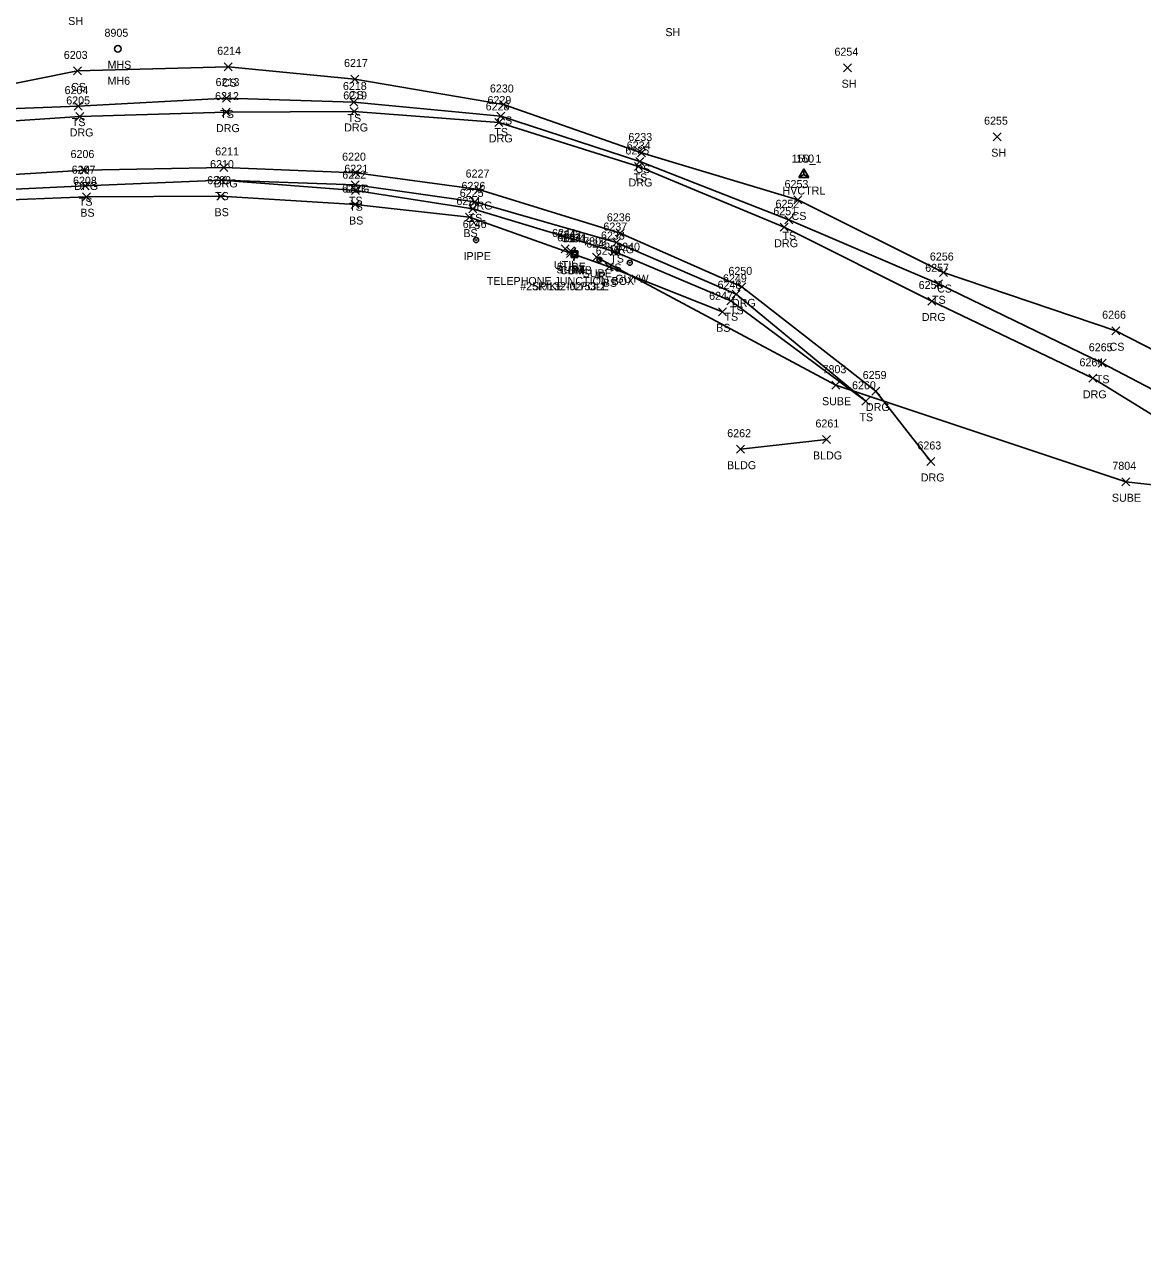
# Model space of a CAD drawing. Extents: x 1678863 to 1683592, y 407783 to 418211.
# Drawn here: x 1679504.2 to 1679783.6, y 409222.9 to 409532.2 of the extents above; entities that cross this region are included whole.
import ezdxf

# ---------------------------------------------------------------- set-up
doc = ezdxf.new("R2010")
doc.units = 0
for name, color, linetype in [('C_A', 7, 'Continuous'), ('C_C', 7, 'Continuous'), ('C_I', 7, 'Continuous'), ('CPBM', 7, 'Continuous'), ('CPSM', 7, 'Continuous'), ('L_A', 7, 'Continuous'), ('L_I', 7, 'Continuous'), ('L_TIC', 7, 'Continuous'), ('LBC', 7, 'Continuous'), ('LELB', 7, 'Continuous'), ('M_A', 7, 'Continuous'), ('M_I', 7, 'Continuous'), ('MPIP', 7, 'Continuous'), ('MPIR', 7, 'Continuous'), ('R_A', 7, 'Continuous'), ('R_I', 7, 'Continuous'), ('R_TIC', 7, 'Continuous'), ('RDG', 7, 'Continuous'), ('U_A', 7, 'Continuous'), ('U_C', 7, 'Continuous'), ('U_I', 7, 'Continuous'), ('U_TIC', 7, 'Continuous'), ('UDEFAULT', 7, 'Continuous'), ('UE', 7, 'Continuous'), ('UP', 7, 'Continuous'), ('UPGW', 7, 'Continuous'), ('USMH', 7, 'Continuous')]:
    doc.layers.add(name, color=color, linetype=linetype)

msp = doc.modelspace()

# ---------------------------------------------------------------- linework, layer by layer
at = {"layer": 'CPBM'}
for p, q in [((1679641.12, 409474.36), (1679641.12, 409475.36)), ((1679641.12, 409475.36), (1679642.12, 409475.36)), ((1679642.12, 409474.36), (1679641.12, 409474.36)), ((1679641.62, 409474.86), (1679641.62, 409474.86)), ((1679641.62, 409474.86), (1679641.62, 409474.86)), ((1679642.12, 409475.36), (1679642.12, 409474.36))]:
    msp.add_line(p, q, dxfattribs=at)
at = {"layer": 'CPSM'}
for p, q in [((1679697.69, 409494.05), (1679698.94, 409496.21)), ((1679697.69, 409494.05), (1679698.94, 409496.21)), ((1679697.69, 409494.05), (1679698.94, 409496.21)), ((1679697.69, 409494.05), (1679698.94, 409496.21)), ((1679697.69, 409494.05), (1679698.94, 409496.21)), ((1679697.69, 409494.05), (1679698.94, 409496.21)), ((1679697.69, 409494.05), (1679698.94, 409496.21)), ((1679697.69, 409494.05), (1679698.94, 409496.21)), ((1679697.69, 409494.05), (1679698.94, 409496.21)), ((1679697.69, 409494.05), (1679698.94, 409494.77)), ((1679697.69, 409494.05), (1679698.94, 409494.77)), ((1679697.69, 409494.05), (1679698.94, 409494.77)), ((1679697.69, 409494.05), (1679698.94, 409494.77)), ((1679697.69, 409494.05), (1679698.94, 409494.77)), ((1679697.69, 409494.05), (1679698.94, 409494.77)), ((1679697.69, 409494.05), (1679698.94, 409494.77)), ((1679697.69, 409494.05), (1679698.94, 409494.77)), ((1679697.69, 409494.05), (1679698.94, 409494.77)), ((1679700.19, 409494.05), (1679698.94, 409496.21)), ((1679698.94, 409494.77), (1679698.94, 409496.21)), ((1679700.19, 409494.05), (1679698.94, 409496.21)), ((1679698.94, 409494.77), (1679698.94, 409496.21)), ((1679700.19, 409494.05), (1679698.94, 409496.21)), ((1679698.94, 409494.77), (1679698.94, 409496.21)), ((1679700.19, 409494.05), (1679698.94, 409496.21)), ((1679698.94, 409494.77), (1679698.94, 409496.21)), ((1679700.19, 409494.05), (1679698.94, 409496.21)), ((1679698.94, 409494.77), (1679698.94, 409496.21)), ((1679700.19, 409494.05), (1679698.94, 409496.21)), ((1679698.94, 409494.77), (1679698.94, 409496.21)), ((1679700.19, 409494.05), (1679698.94, 409496.21)), ((1679698.94, 409494.77), (1679698.94, 409496.21)), ((1679700.19, 409494.05), (1679698.94, 409496.21)), ((1679698.94, 409494.77), (1679698.94, 409496.21)), ((1679700.19, 409494.05), (1679698.94, 409496.21)), ((1679698.94, 409494.77), (1679698.94, 409496.21)), ((1679698.94, 409494.77), (1679698.94, 409494.77)), ((1679698.94, 409494.77), (1679700.19, 409494.05)), ((1679698.94, 409494.77), (1679698.94, 409494.77)), ((1679698.94, 409494.77), (1679700.19, 409494.05)), ((1679698.94, 409494.77), (1679698.94, 409494.77)), ((1679698.94, 409494.77), (1679700.19, 409494.05)), ((1679698.94, 409494.77), (1679698.94, 409494.77)), ((1679698.94, 409494.77), (1679700.19, 409494.05)), ((1679698.94, 409494.77), (1679698.94, 409494.77)), ((1679698.94, 409494.77), (1679700.19, 409494.05)), ((1679698.94, 409494.77), (1679698.94, 409494.77)), ((1679698.94, 409494.77), (1679700.19, 409494.05)), ((1679698.94, 409494.77), (1679698.94, 409494.77)), ((1679698.94, 409494.77), (1679700.19, 409494.05)), ((1679698.94, 409494.77), (1679698.94, 409494.77)), ((1679698.94, 409494.77), (1679700.19, 409494.05)), ((1679698.94, 409494.77), (1679698.94, 409494.77)), ((1679698.94, 409494.77), (1679700.19, 409494.05)), ((1679697.69, 409494.05), (1679700.19, 409494.05)), ((1679697.69, 409494.05), (1679700.19, 409494.05)), ((1679697.69, 409494.05), (1679700.19, 409494.05)), ((1679697.69, 409494.05), (1679700.19, 409494.05)), ((1679697.69, 409494.05), (1679700.19, 409494.05)), ((1679697.69, 409494.05), (1679700.19, 409494.05)), ((1679697.69, 409494.05), (1679700.19, 409494.05)), ((1679697.69, 409494.05), (1679700.19, 409494.05)), ((1679697.69, 409494.05), (1679700.19, 409494.05))]:
    msp.add_line(p, q, dxfattribs=at)
at = {"layer": 'L_TIC'}
for points in [[(1679554.06, 409520.72), (1679556.06, 409522.72)], [(1679556.06, 409520.72), (1679554.06, 409522.72)], [(1679708.92, 409520.48), (1679710.92, 409522.48)], [(1679710.92, 409520.48), (1679708.92, 409522.48)], [(1679516.35, 409519.68), (1679518.35, 409521.68)], [(1679518.35, 409519.68), (1679516.35, 409521.68)], [(1679585.76, 409517.66), (1679587.76, 409519.66)], [(1679587.76, 409517.66), (1679585.76, 409519.66)], [(1679553.65, 409512.89), (1679555.65, 409514.89)], [(1679555.65, 409512.89), (1679553.65, 409514.89)], [(1679585.48, 409511.91), (1679587.48, 409513.91)], [(1679587.48, 409511.91), (1679585.48, 409513.91)], [(1679622.89, 409511.29), (1679624.89, 409513.29)], [(1679624.89, 409511.29), (1679622.89, 409513.29)], [(1679516.55, 409510.88), (1679518.55, 409512.88)], [(1679518.55, 409510.88), (1679516.55, 409512.88)], [(1679622.19, 409508.4), (1679624.19, 409510.4)], [(1679624.19, 409508.4), (1679622.19, 409510.4)], [(1679746.33, 409503.24), (1679748.33, 409505.24)], [(1679748.33, 409503.24), (1679746.33, 409505.24)], [(1679657.4, 409499.17), (1679659.4, 409501.17)], [(1679659.4, 409499.17), (1679657.4, 409501.17)], [(1679657, 409497.05), (1679659, 409499.05)], [(1679659, 409497.05), (1679657, 409499.05)], [(1679518.31, 409490.99), (1679520.31, 409492.99)], [(1679520.31, 409490.99), (1679518.31, 409492.99)], [(1679552.37, 409492.38), (1679554.37, 409494.38)], [(1679554.37, 409492.38), (1679552.37, 409494.38)], [(1679552.37, 409492.38), (1679554.37, 409494.38)], [(1679554.37, 409492.38), (1679552.37, 409494.38)], [(1679585.84, 409491.23), (1679587.84, 409493.23)], [(1679587.84, 409491.23), (1679585.84, 409493.23)], [(1679585.89, 409489.75), (1679587.89, 409491.75)], [(1679587.89, 409489.75), (1679585.89, 409491.75)], [(1679518.65, 409488.23), (1679520.65, 409490.23)], [(1679520.65, 409488.23), (1679518.65, 409490.23)], [(1679552.2, 409488.37), (1679554.2, 409490.37)], [(1679554.2, 409488.37), (1679552.2, 409490.37)], [(1679585.83, 409486.28), (1679587.83, 409488.28)], [(1679587.83, 409486.28), (1679585.83, 409488.28)], [(1679615.75, 409486.94), (1679617.75, 409488.94)], [(1679617.75, 409486.94), (1679615.75, 409488.94)], [(1679696.46, 409487.42), (1679698.46, 409489.42)], [(1679698.46, 409487.42), (1679696.46, 409489.42)], [(1679615.25, 409485.17), (1679617.25, 409487.17)], [(1679617.25, 409485.17), (1679615.25, 409487.17)], [(1679614.42, 409483.14), (1679616.42, 409485.14)], [(1679616.42, 409483.14), (1679614.42, 409485.14)], [(1679694.2, 409482.47), (1679696.2, 409484.47)], [(1679696.2, 409482.47), (1679694.2, 409484.47)], [(1679650.56, 409474.53), (1679652.56, 409476.53)], [(1679652.56, 409474.53), (1679650.56, 409476.53)], [(1679651.16, 409476.77), (1679653.16, 409478.77)], [(1679653.16, 409476.77), (1679651.16, 409478.77)], [(1679649.26, 409470.71), (1679651.26, 409472.71)], [(1679651.26, 409470.71), (1679649.26, 409472.71)], [(1679732.85, 409469.28), (1679734.85, 409471.28)], [(1679734.85, 409469.28), (1679732.85, 409471.28)], [(1679731.61, 409466.46), (1679733.61, 409468.46)], [(1679733.61, 409466.46), (1679731.61, 409468.46)], [(1679679.71, 409462.23), (1679681.71, 409464.23)], [(1679681.71, 409462.23), (1679679.71, 409464.23)], [(1679681.07, 409463.84), (1679683.07, 409465.84)], [(1679683.07, 409463.84), (1679681.07, 409465.84)], [(1679677.6, 409459.46), (1679679.6, 409461.46)], [(1679679.6, 409459.46), (1679677.6, 409461.46)], [(1679775.94, 409454.73), (1679777.94, 409456.73)], [(1679777.94, 409454.73), (1679775.94, 409456.73)], [(1679772.55, 409446.6), (1679774.55, 409448.6)], [(1679774.55, 409446.6), (1679772.55, 409448.6)], [(1679713.46, 409437.1), (1679715.46, 409439.1)], [(1679715.46, 409437.1), (1679713.46, 409439.1)], [(1679713.46, 409437.1), (1679715.46, 409439.1)], [(1679715.46, 409437.1), (1679713.46, 409439.1)], [(1679703.66, 409427.55), (1679705.66, 409429.55)], [(1679705.66, 409427.55), (1679703.66, 409429.55)], [(1679682.17, 409425.12), (1679684.17, 409427.12)], [(1679684.17, 409425.12), (1679682.17, 409427.12)]]:
    msp.add_lwpolyline(points, dxfattribs=at)
at = {"layer": 'LBC'}
msp.add_lwpolyline([(1679704.66, 409428.55), (1679683.17, 409426.12)], dxfattribs=at)
at = {"layer": 'LELB'}
for points in [[(1679305.95, 409537.26), (1679317.44, 409526.86), (1679335.4, 409520.07), (1679344.31, 409516.71), (1679350.6, 409515.86), (1679378.56, 409512.89), (1679403.67, 409511.84), (1679434.09, 409510.57), (1679446.83, 409507.71), (1679465.11, 409513.87), (1679484.66, 409514.14), (1679517.35, 409520.68), (1679555.06, 409521.72), (1679586.76, 409518.66), (1679623.89, 409512.29), (1679658.4, 409500.17), (1679697.46, 409488.42), (1679733.85, 409470.28), (1679776.94, 409455.73), (1679804.5, 409441.59)], [(1679304.26, 409533.54), (1679315.87, 409524.05), (1679333.13, 409516.45), (1679350.4, 409512.46), (1679378.07, 409510.17), (1679404.61, 409508.8), (1679432.97, 409508), (1679446.42, 409507.11), (1679464.31, 409510.03), (1679484.56, 409510.64), (1679517.55, 409511.88), (1679554.65, 409513.89), (1679586.48, 409512.91), (1679623.19, 409509.4), (1679658, 409498.05), (1679695.2, 409483.47), (1679732.61, 409467.46), (1679773.55, 409447.6), (1679800.48, 409433.53)], [(1679282, 409484.12), (1679286.62, 409495.42), (1679295.06, 409500.7), (1679306.39, 409501.55), (1679324.4, 409496.56), (1679344.62, 409492.66), (1679371.89, 409490.35), (1679403.53, 409489.08), (1679444.63, 409489.99), (1679485.75, 409490.4), (1679519.31, 409491.99), (1679553.37, 409493.38), (1679586.84, 409492.23), (1679616.75, 409487.94), (1679652.16, 409477.77), (1679682.07, 409464.84), (1679714.46, 409438.1)], [(1679290.09, 409482.41), (1679299.3, 409494.32), (1679321.5, 409488.92), (1679344.84, 409490.76), (1679371.94, 409488.06), (1679404.95, 409486.11), (1679444.56, 409487.3), (1679450.19, 409487.49), (1679485.85, 409487.91), (1679519.65, 409489.23), (1679553.2, 409489.37), (1679586.83, 409487.28), (1679615.42, 409484.14), (1679650.26, 409471.71), (1679678.6, 409460.46)], [(1679553.37, 409493.38), (1679586.89, 409490.75), (1679616.25, 409486.17), (1679651.56, 409475.53), (1679680.71, 409463.23), (1679714.46, 409438.1)]]:
    msp.add_lwpolyline(points, dxfattribs=at)
at = {"layer": 'MPIP'}
for radius in [0.625, 0.0833]:
    msp.add_circle((1679617.05, 409478.4), radius, dxfattribs=at)
at = {"layer": 'MPIR'}
for radius in [0.625, 0.0833]:
    msp.add_circle((1679647.87, 409473.5), radius, dxfattribs=at)
at = {"layer": 'R_TIC'}
for points in [[(1679516.95, 409508.3), (1679518.95, 409510.3)], [(1679518.95, 409508.3), (1679516.95, 409510.3)], [(1679553.52, 409509.38), (1679555.52, 409511.38)], [(1679555.52, 409509.38), (1679553.52, 409511.38)], [(1679585.57, 409509.55), (1679587.57, 409511.55)], [(1679587.57, 409509.55), (1679585.57, 409511.55)], [(1679621.74, 409506.82), (1679623.74, 409508.82)], [(1679623.74, 409506.82), (1679621.74, 409508.82)], [(1679552.99, 409495.56), (1679554.99, 409497.56)], [(1679554.99, 409495.56), (1679552.99, 409497.56)], [(1679656.66, 409495.79), (1679658.66, 409497.79)], [(1679658.66, 409495.79), (1679656.66, 409497.79)], [(1679518.1, 409494.91), (1679520.1, 409496.91)], [(1679520.1, 409494.91), (1679518.1, 409496.91)], [(1679585.93, 409494.24), (1679587.93, 409496.24)], [(1679587.93, 409494.24), (1679585.93, 409496.24)], [(1679616.73, 409490.03), (1679618.73, 409492.03)], [(1679618.73, 409490.03), (1679616.73, 409492.03)], [(1679693.07, 409480.62), (1679695.07, 409482.62)], [(1679695.07, 409480.62), (1679693.07, 409482.62)], [(1679652.09, 409479.09), (1679654.09, 409481.09)], [(1679654.09, 409479.09), (1679652.09, 409481.09)], [(1679682.5, 409465.7), (1679684.5, 409467.7)], [(1679684.5, 409465.7), (1679682.5, 409467.7)], [(1679729.97, 409462.16), (1679731.97, 409464.16)], [(1679731.97, 409462.16), (1679729.97, 409464.16)], [(1679770.23, 409442.84), (1679772.23, 409444.84)], [(1679772.23, 409442.84), (1679770.23, 409444.84)], [(1679716, 409439.66), (1679718, 409441.66)], [(1679718, 409439.66), (1679716, 409441.66)], [(1679729.72, 409422.05), (1679731.72, 409424.05)], [(1679731.72, 409422.05), (1679729.72, 409424.05)]]:
    msp.add_lwpolyline(points, dxfattribs=at)
at = {"layer": 'RDG'}
for points in [[(1679295.03, 409550.59), (1679297.1, 409542.73), (1679303.32, 409531.13), (1679315.01, 409521.66), (1679332.29, 409513.92), (1679350.07, 409509.87), (1679377.78, 409507.16), (1679404.7, 409506.4), (1679431.94, 409505.14), (1679446.95, 409505.02), (1679463.92, 409505.45), (1679484.26, 409507.05), (1679517.95, 409509.3), (1679554.52, 409510.38), (1679586.57, 409510.55), (1679622.74, 409507.82), (1679657.66, 409496.79), (1679694.07, 409481.62), (1679730.97, 409463.16), (1679771.23, 409443.84)], [(1679282.64, 409496.81), (1679288.59, 409501.13), (1679298.56, 409504.89), (1679306.59, 409505.09), (1679325.99, 409500.79), (1679345.8, 409495.93), (1679371.93, 409494.03), (1679402.45, 409492.41), (1679444.96, 409492.59), (1679485.21, 409493.75), (1679519.1, 409495.91), (1679553.99, 409496.56), (1679586.93, 409495.24), (1679617.73, 409491.03), (1679653.09, 409480.09), (1679683.5, 409466.7), (1679717, 409440.66), (1679730.72, 409423.05)], [(1679771.23, 409443.84), (1679789.5, 409432.61)]]:
    msp.add_lwpolyline(points, dxfattribs=at)
at = {"layer": 'U_TIC'}
for points in [[(1679639.61, 409474.07), (1679641.61, 409476.07)], [(1679641.61, 409474.07), (1679639.61, 409476.07)], [(1679639.65, 409474.72), (1679641.65, 409476.72)], [(1679641.65, 409474.72), (1679639.65, 409476.72)], [(1679646.13, 409473.1), (1679648.13, 409475.1)], [(1679648.13, 409473.1), (1679646.13, 409475.1)], [(1679705.97, 409441.12), (1679707.97, 409443.12)], [(1679707.97, 409441.12), (1679705.97, 409443.12)], [(1679778.43, 409416.98), (1679780.43, 409418.98)], [(1679780.43, 409416.98), (1679778.43, 409418.98)]]:
    msp.add_lwpolyline(points, dxfattribs=at)
at = {"layer": 'UDEFAULT'}
for points in [[(1679638.32, 409475.17), (1679640.32, 409477.17)], [(1679640.32, 409475.17), (1679638.32, 409477.17)]]:
    msp.add_lwpolyline(points, dxfattribs=at)
at = {"layer": 'UE'}
msp.add_lwpolyline([(1679647.13, 409474.1), (1679706.97, 409442.12), (1679779.43, 409417.98), (1679860.01, 409409.02), (1679992.93, 409384.11), (1680024.94, 409378.43), (1680045.36, 409367.07), (1680068.92, 409363.05), (1680092.68, 409364.94), (1680171.99, 409354.04), (1680191.1, 409351.39), (1680214.58, 409340.84), (1680248.48, 409278.96), (1680262.62, 409244.41), (1680272.9, 409222.87)], dxfattribs=at)
at = {"layer": 'UP'}
for p, q in [((1679641.85, 409476.52), (1679641.6, 409475.69)), ((1679640.77, 409474.02), (1679640.77, 409475.69)), ((1679640.77, 409475.69), (1679642.44, 409475.69)), ((1679642.44, 409474.02), (1679640.77, 409474.02)), ((1679641.35, 409473.19), (1679641.6, 409474.02)), ((1679641.6, 409474.86), (1679641.6, 409474.86)), ((1679642.44, 409475.69), (1679642.44, 409474.02))]:
    msp.add_line(p, q, dxfattribs=at)
msp.add_circle((1679641.6, 409474.86), 0.833, dxfattribs=at)
at = {"layer": 'UPGW'}
for radius in [0.625, 0.0833]:
    msp.add_circle((1679655.45, 409472.73), radius, dxfattribs=at)
at = {"layer": 'USMH'}
for p, q in [((1679527.48, 409526.22), (1679527.48, 409526.22)), ((1679528.31, 409526.22), (1679528.31, 409526.22))]:
    msp.add_line(p, q, dxfattribs=at)
msp.add_circle((1679527.48, 409526.22), 0.833, dxfattribs=at)

# ---------------------------------------------------------------- texts
at = {"layer": 'C_A'}
for s, p in [('HVCTRL', (1679693.63, 409489.77)), ('HVCTRL', (1679693.63, 409489.77)), ('HVCTRL', (1679693.63, 409489.77)), ('HVCTRL', (1679693.63, 409489.77)), ('HVCTRL', (1679693.63, 409489.77)), ('HVCTRL', (1679693.63, 409489.77)), ('HVCTRL', (1679693.63, 409489.77)), ('HVCTRL', (1679693.63, 409489.77)), ('HVCTRL', (1679693.63, 409489.77)), ('BM', (1679639.94, 409469.86))]:
    msp.add_text(s, height=2, dxfattribs=at).set_placement(p)
at = {"layer": 'C_C'}
msp.add_text('SPIKE IN POLE', height=2, dxfattribs=at).set_placement((1679631.05, 409465.86))
at = {"layer": 'C_I'}
for s, p in [('150_1', (1679695.92, 409497.77)), ('150', (1679697.06, 409497.77)), ('150', (1679697.06, 409497.77)), ('150', (1679697.06, 409497.77)), ('150', (1679697.06, 409497.77)), ('150', (1679697.06, 409497.77)), ('150', (1679697.06, 409497.77)), ('150', (1679697.06, 409497.77)), ('150', (1679697.06, 409497.77)), ('6554', (1679638.31, 409477.86))]:
    msp.add_text(s, height=2, dxfattribs=at).set_placement(p)
at = {"layer": 'L_A'}
for s, p in [('SH', (1679515.06, 409532.17)), ('SH', (1679664.36, 409529.38)), ('CS', (1679515.79, 409515.68)), ('CS', (1679553.51, 409516.72)), ('SH', (1679708.41, 409516.48)), ('CS', (1679585.2, 409513.66)), ('TS', (1679553.06, 409508.89)), ('TS', (1679584.89, 409507.91)), ('TS', (1679515.96, 409506.88)), ('CS', (1679622.33, 409507.29)), ('TS', (1679621.6, 409504.4)), ('SH', (1679745.82, 409499.24)), ('TS', (1679656.41, 409493.05)), ('CS', (1679656.85, 409495.17)), ('TS', (1679517.72, 409486.99)), ('TS', (1679551.78, 409488.38)), ('TS', (1679551.78, 409488.38)), ('TS', (1679585.25, 409487.23)), ('BS', (1679518.09, 409484.23)), ('BS', (1679551.64, 409484.37)), ('TS', (1679585.3, 409485.75)), ('CS', (1679695.9, 409483.42)), ('BS', (1679585.27, 409482.28)), ('TS', (1679614.66, 409481.17)), ('TS', (1679615.16, 409482.94)), ('BS', (1679613.86, 409479.14)), ('TS', (1679693.61, 409478.47)), ('TS', (1679650.57, 409472.77)), ('TS', (1679649.97, 409470.53)), ('BS', (1679648.7, 409466.71)), ('CS', (1679732.29, 409465.28)), ('TS', (1679731.01, 409462.46)), ('TS', (1679680.48, 409459.84)), ('BS', (1679677.04, 409455.46)), ('TS', (1679679.12, 409458.23)), ('CS', (1679775.39, 409450.73)), ('TS', (1679771.96, 409442.6)), ('TS', (1679712.87, 409433.1)), ('TS', (1679712.87, 409433.1)), ('BLDG', (1679701.25, 409423.55)), ('BLDG', (1679679.76, 409421.12))]:
    msp.add_text(s, height=2, dxfattribs=at).set_placement(p)
at = {"layer": 'L_I'}
for s, p in [('6203', (1679513.96, 409523.68)), ('6214', (1679552.32, 409524.72)), ('6254', (1679706.62, 409524.48)), ('6217', (1679584.02, 409521.66)), ('6204', (1679514.16, 409514.88)), ('6213', (1679551.91, 409516.89)), ('6218', (1679583.74, 409515.91)), ('6230', (1679620.49, 409515.29)), ('6229', (1679619.88, 409512.4)), ('6255', (1679744.02, 409507.24)), ('6233', (1679655.1, 409503.17)), ('6234', (1679654.69, 409501.05)), ('6210', (1679550.54, 409496.38)), ('6210', (1679550.54, 409496.38)), ('6207', (1679515.93, 409494.99)), ('6222', (1679583.59, 409493.75)), ('6221', (1679584.1, 409495.23)), ('6208', (1679516.27, 409492.23)), ('6209', (1679549.81, 409492.37)), ('6223', (1679583.52, 409490.28)), ('6226', (1679613.39, 409490.94)), ('6253', (1679694.15, 409491.42)), ('6224', (1679612.11, 409487.14)), ('6225', (1679612.94, 409489.17)), ('6252', (1679691.89, 409486.47)), ('6237', (1679648.85, 409480.77)), ('6238', (1679648.25, 409478.53)), ('6239', (1679646.95, 409474.71)), ('6256', (1679730.48, 409473.28)), ('6249', (1679678.75, 409467.84)), ('6257', (1679729.3, 409470.46)), ('6248', (1679677.4, 409466.23)), ('6247', (1679675.29, 409463.46)), ('6266', (1679773.54, 409458.73)), ('6265', (1679770.2, 409450.6)), ('6260', (1679711.02, 409441.1)), ('6260', (1679711.02, 409441.1)), ('6261', (1679701.87, 409431.55)), ('6262', (1679679.81, 409429.12))]:
    msp.add_text(s, height=2, dxfattribs=at).set_placement(p)
at = {"layer": 'M_A'}
for s, p in [('IPIPE', (1679613.89, 409473.4)), ('IP', (1679646.91, 409468.5))]:
    msp.add_text(s, height=2, dxfattribs=at).set_placement(p)
at = {"layer": 'M_I'}
for s, p in [('6246', (1679613.69, 409481.4)), ('6245', (1679644.56, 409476.5))]:
    msp.add_text(s, height=2, dxfattribs=at).set_placement(p)
at = {"layer": 'R_A'}
for p in [(1679552.01, 409505.38), (1679584.06, 409505.55), (1679515.44, 409504.3), (1679620.23, 409502.82), (1679516.58, 409490.91), (1679551.48, 409491.56), (1679584.42, 409490.24), (1679655.15, 409491.79), (1679615.21, 409486.03), (1679650.58, 409475.09), (1679691.56, 409476.62), (1679680.99, 409461.7), (1679728.46, 409458.16), (1679768.72, 409438.84), (1679714.49, 409435.66), (1679728.2, 409418.05)]:
    msp.add_text('DRG', height=2, dxfattribs=at).set_placement(p)
at = {"layer": 'R_I'}
for s, p in [('6205', (1679514.57, 409512.3)), ('6212', (1679551.78, 409513.38)), ('6219', (1679583.82, 409513.55)), ('6228', (1679619.43, 409510.82)), ('6206', (1679515.65, 409498.91)), ('6211', (1679551.82, 409499.56)), ('6235', (1679654.35, 409499.79)), ('6220', (1679583.54, 409498.24)), ('6227', (1679614.42, 409494.03)), ('6251', (1679691.33, 409484.62)), ('6236', (1679649.73, 409483.09)), ('6250', (1679680.11, 409469.7)), ('6258', (1679727.67, 409466.16)), ('6264', (1679767.88, 409446.84)), ('6259', (1679713.68, 409443.66)), ('6263', (1679727.36, 409426.05))]:
    msp.add_text(s, height=2, dxfattribs=at).set_placement(p)
at = {"layer": 'U_A'}
for s, p in [('MHS', (1679524.9, 409521.22)), ('UTIL', (1679636.49, 409471.17)), ('SUBT', (1679637.11, 409470.07)), ('SUBE', (1679637.18, 409470.72)), ('COMB', (1679637.99, 409469.86)), ('SUBE', (1679643.67, 409469.1)), ('GUYW', (1679651.84, 409467.73)), ('SUBE', (1679703.51, 409437.12)), ('SUBE', (1679775.97, 409412.98))]:
    msp.add_text(s, height=2, dxfattribs=at).set_placement(p)
at = {"layer": 'U_C'}
for s, p in [('MH6', (1679524.89, 409517.22)), ('TELEPHONE JUNCTION BOX', (1679619.7, 409467.17)), ('#25K/132-02/53-2', (1679628.06, 409465.86))]:
    msp.add_text(s, height=2, dxfattribs=at).set_placement(p)
at = {"layer": 'U_I'}
for s, p in [('8905', (1679524.14, 409529.22)), ('6244', (1679636.02, 409479.17)), ('6243', (1679637.3, 409478.07)), ('6242', (1679637.34, 409478.72)), ('6241', (1679638.86, 409477.86)), ('7802', (1679643.8, 409477.1)), ('6240', (1679652.05, 409475.73)), ('7803', (1679703.64, 409445.12)), ('7804', (1679776.09, 409420.98))]:
    msp.add_text(s, height=2, dxfattribs=at).set_placement(p)

doc.saveas('drawing.dxf')
